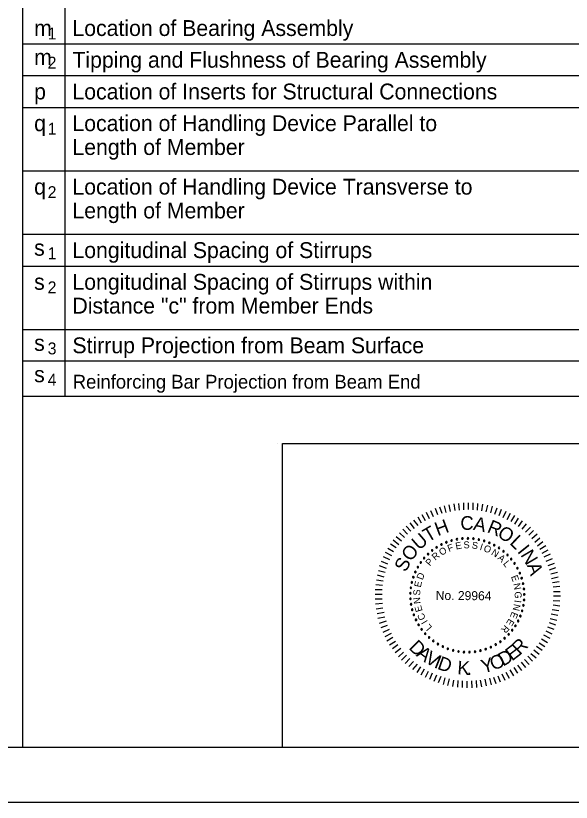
# Model space of a CAD drawing. Extents: x -55.6 to -19.5, y -5.1 to 16.9.
# Drawn here: x -35.36 to -30.34, y -5.09 to 2.04 of the extents above; entities that cross this region are included whole.
import ezdxf

# ---------------------------------------------------------------- set-up
doc = ezdxf.new("R2010")
doc.units = 0
for name, color, linetype in [('BR_BORDER LINES', 7, 'Continuous'), ('BR_TABLE LINES', 7, 'Continuous'), ('BR_TEXT', 7, 'Continuous'), ('Default', 7, 'Continuous'), ('Level 31', 7, 'Continuous')]:
    doc.layers.add(name, color=color, linetype=linetype)

msp = doc.modelspace()

# ---------------------------------------------------------------- linework, layer by layer
at = {"layer": 'BR_BORDER LINES'}
for p, q in [((-35.3047, 8.7992), (-35.3047, -4.5917)), ((-35.3047, -1.4104), (-25.9542, -1.4104)), ((-32.9495, -1.8415), (-27.5843, -1.8415)), ((-32.9495, -4.5916), (-32.9495, -1.8415)), ((-53.7501, -4.5917), (-20.084, -4.5917))]:
    msp.add_line(p, q, dxfattribs=at)
at = {"layer": 'BR_TABLE LINES'}
for p, q in [((-34.9214, 8.7992), (-34.9214, -1.4104)), ((-35.3047, 1.7804), (-25.9542, 1.7804)), ((-35.3047, 1.4929), (-25.9542, 1.4929)), ((-35.3047, 1.2054), (-25.9542, 1.2054)), ((-35.3047, 0.6304), (-25.9542, 0.6304)), ((-35.3047, 0.0554), (-25.9542, 0.0554)), ((-35.3047, -0.2321), (-25.9542, -0.2321)), ((-35.3047, -0.8071), (-25.9542, -0.8071)), ((-35.3047, -1.0912), (-25.9542, -1.0912))]:
    msp.add_line(p, q, dxfattribs=at)
at = {"layer": 'BR_TEXT'}
for p, q in [((-31.5048, -2.4758), (-31.5266, -2.4182)), ((-31.4686, -2.4658), (-31.4818, -2.4048)), ((-31.4273, -2.4559), (-31.4415, -2.3966)), ((-31.3878, -2.4485), (-31.3967, -2.3875)), ((-31.3483, -2.4445), (-31.3521, -2.3836)), ((-31.3088, -2.4423), (-31.3083, -2.3779)), ((-31.2667, -2.4401), (-31.2662, -2.3783)), ((-31.2247, -2.443), (-31.2224, -2.3786)), ((-31.1844, -2.4459), (-31.1796, -2.385)), ((-31.1458, -2.4505), (-31.135, -2.3897)), ((-31.1055, -2.4586), (-31.0913, -2.3994)), ((-31.0645, -2.4692), (-31.0485, -2.4084)), ((-31.0276, -2.4798), (-31.0057, -2.4225)), ((-31.6546, -2.5398), (-31.685, -2.4855)), ((-31.6201, -2.5221), (-31.6463, -2.4661)), ((-31.5831, -2.5052), (-31.6067, -2.4493)), ((-31.5443, -2.4884), (-31.5653, -2.4299)), ((-30.9883, -2.493), (-30.9663, -2.4348)), ((-30.9524, -2.5105), (-30.9245, -2.4549)), ((-30.9165, -2.5279), (-30.8851, -2.4724)), ((-30.8788, -2.5463), (-30.8466, -2.4924)), ((-31.7547, -2.6102), (-31.7946, -2.5601)), ((-31.721, -2.5848), (-31.7601, -2.5338)), ((-31.69, -2.5636), (-31.7204, -2.5092)), ((-30.8456, -2.5705), (-30.8117, -2.5167)), ((-30.8123, -2.5923), (-30.7758, -2.5419)), ((-31.817, -2.662), (-31.8612, -2.6179)), ((-31.7876, -2.6348), (-31.8292, -2.5899)), ((-30.7799, -2.6183), (-30.7392, -2.5688)), ((-30.7484, -2.6434), (-30.7051, -2.5992)), ((-30.7203, -2.6711), (-30.677, -2.6277)), ((-31.8715, -2.7243), (-31.921, -2.6852)), ((-31.8464, -2.6927), (-31.8898, -2.6503)), ((-30.6922, -2.7023), (-30.6447, -2.6606)), ((-30.665, -2.7342), (-30.6184, -2.696)), ((-31.9192, -2.7865), (-31.973, -2.7535)), ((-31.8975, -2.7575), (-31.947, -2.7176)), ((-30.6412, -2.7679), (-30.592, -2.7288)), ((-30.6192, -2.7972), (-30.5666, -2.7651)), ((-31.961, -2.8574), (-32.0174, -2.8295)), ((-31.9436, -2.8232), (-31.9974, -2.791)), ((-30.5972, -2.8343), (-30.5437, -2.803)), ((-30.5794, -2.8688), (-30.5217, -2.8418)), ((-31.996, -2.9326), (-32.0541, -2.9107)), ((-31.9785, -2.8942), (-32.0358, -2.8688)), ((-30.5617, -2.9059), (-30.5049, -2.8814)), ((-32.0083, -2.9729), (-32.0699, -2.9501)), ((-30.5449, -2.9446), (-30.4881, -2.9236)), ((-30.5315, -2.985), (-30.4738, -2.9632)), ((-32.0279, -3.0508), (-32.0904, -3.0349)), ((-32.0206, -3.0088), (-32.0815, -2.9937)), ((-30.5215, -3.0212), (-30.4613, -3.0071)), ((-30.5133, -3.0633), (-30.453, -3.0484)), ((-32.0431, -3.1279), (-32.1048, -3.1206)), ((-32.0384, -3.0868), (-32.0993, -3.0785)), ((-30.5049, -3.0994), (-30.4457, -3.0922)), ((-30.4984, -3.1407), (-30.4374, -3.1343)), ((-32.046, -3.1674), (-32.1103, -3.1668)), ((-30.4971, -3.1802), (-30.437, -3.1807)), ((-32.0467, -3.2515), (-32.111, -3.2526)), ((-32.048, -3.2085), (-32.1107, -3.208)), ((-30.4977, -3.2642), (-30.4377, -3.2665)), ((-30.4948, -3.2213), (-30.4339, -3.2218)), ((-32.0444, -3.2901), (-32.1062, -3.2973)), ((-32.0404, -3.3313), (-32.1015, -3.3403)), ((-30.507, -3.344), (-30.4479, -3.3539)), ((-30.4998, -3.3029), (-30.4389, -3.3111)), ((-32.0305, -3.3709), (-32.0932, -3.3841)), ((-32.024, -3.413), (-32.085, -3.4271)), ((-30.5159, -3.3834), (-30.4559, -3.3976)), ((-32.0123, -3.45), (-32.0742, -3.4709)), ((-32.0006, -3.4887), (-32.0591, -3.5097)), ((-30.5354, -3.4622), (-30.4781, -3.4841)), ((-30.5248, -3.4254), (-30.4649, -3.4405)), ((-31.9837, -3.5257), (-32.0414, -3.5527)), ((-31.9669, -3.5619), (-32.0237, -3.5915)), ((-30.5669, -3.5374), (-30.5105, -3.5653)), ((-30.5495, -3.5007), (-30.493, -3.5226)), ((-31.95, -3.599), (-32.0043, -3.6303)), ((-30.6036, -3.6101), (-30.5506, -3.6423)), ((-30.5853, -3.5733), (-30.528, -3.6038)), ((-31.9263, -3.6361), (-31.9806, -3.6674)), ((-31.905, -3.6654), (-31.9551, -3.7019)), ((-31.8796, -3.6991), (-31.9297, -3.7382)), ((-30.6487, -3.6758), (-30.6001, -3.7131)), ((-30.6262, -3.6468), (-30.5741, -3.679)), ((-31.855, -3.7328), (-31.8991, -3.7736)), ((-31.826, -3.7588), (-31.871, -3.8039)), ((-30.7293, -3.7678), (-30.6868, -3.8136)), ((-30.7008, -3.7423), (-30.6539, -3.7839)), ((-30.6731, -3.7091), (-30.6271, -3.7489)), ((-31.7971, -3.789), (-31.8395, -3.835)), ((-31.7647, -3.815), (-31.8054, -3.8619)), ((-31.7314, -3.8411), (-31.7713, -3.8888)), ((-30.8227, -3.8486), (-30.787, -3.8969)), ((-30.7898, -3.8231), (-30.7499, -3.8706)), ((-30.7579, -3.7976), (-30.7154, -3.8443)), ((-31.7007, -3.8628), (-31.732, -3.9148)), ((-31.6657, -3.8854), (-31.697, -3.9392)), ((-31.6315, -3.9054), (-31.6586, -3.961)), ((-30.9279, -3.9112), (-30.8975, -3.9672)), ((-30.89, -3.8918), (-30.8587, -3.9461)), ((-30.8563, -3.8698), (-30.8233, -3.9223)), ((-31.5948, -3.9228), (-31.6193, -3.9784)), ((-31.5563, -3.9403), (-31.5782, -3.9968)), ((-31.5169, -3.9527), (-31.5398, -4.0108)), ((-31.481, -3.965), (-31.4952, -4.0241)), ((-31.4399, -3.9722), (-31.455, -4.0339)), ((-31.4005, -3.9837), (-31.4104, -4.0419)), ((-31.361, -3.9883), (-31.3659, -4.05)), ((-31.3216, -3.9912), (-31.3221, -4.053)), ((-31.1972, -3.9896), (-31.1934, -4.0515)), ((-31.1585, -3.9857), (-31.1487, -4.0441)), ((-31.1181, -3.9748), (-31.1049, -4.0368)), ((-31.0768, -3.9683), (-31.0618, -4.0277)), ((-31.0398, -3.9566), (-31.0189, -4.0151)), ((-31.0003, -3.9449), (-30.9793, -4.0017)), ((-30.9641, -3.9281), (-30.9371, -3.9841)), ((-31.2796, -3.9941), (-31.2801, -4.0551)), ((-31.2375, -3.9919), (-31.2363, -4.0537))]:
    msp.add_line(p, q, dxfattribs=at)
for centre, start, end in [((-31.3702, -2.7086), 10.60376, 190.60376), ((-31.3702, -2.7086), 190.60376, 10.60376), ((-31.3208, -2.7019), 5.06529, 185.06529), ((-31.3208, -2.7019), 185.06529, 5.06529), ((-31.271, -2.7), 359.52683, 179.52683), ((-31.271, -2.7), 179.52683, 359.52683), ((-31.2213, -2.7029), 353.98837, 173.98837), ((-31.2213, -2.7029), 173.98837, 353.98837), ((-31.1721, -2.7106), 348.44991, 168.44991), ((-31.5545, -2.7814), 32.7576, 212.7576), ((-31.5545, -2.7814), 212.7576, 32.7576), ((-31.5113, -2.7566), 27.21914, 207.21914), ((-31.5113, -2.7566), 207.21914, 27.21914), ((-31.4659, -2.7361), 21.68068, 201.68068), ((-31.4659, -2.7361), 201.68068, 21.68068), ((-31.4187, -2.72), 16.14222, 196.14222), ((-31.4187, -2.72), 196.14222, 16.14222), ((-31.1721, -2.7106), 168.44991, 348.44991), ((-31.1238, -2.723), 162.91145, 342.91145), ((-31.1238, -2.723), 342.91145, 162.91145), ((-31.077, -2.74), 157.37299, 337.37299), ((-31.077, -2.74), 337.37299, 157.37299), ((-31.032, -2.7615), 151.83453, 331.83453), ((-31.032, -2.7615), 331.83453, 151.83453), ((-31.6327, -2.843), 43.83453, 223.83453), ((-31.6327, -2.843), 223.83453, 43.83453), ((-31.5951, -2.8103), 38.29606, 218.29606), ((-31.5951, -2.8103), 218.29606, 38.29606), ((-30.9893, -2.7872), 146.29606, 326.29606), ((-30.9893, -2.7872), 326.29606, 146.29606), ((-30.9493, -2.8169), 140.7576, 320.7576), ((-30.9493, -2.8169), 320.7576, 140.7576), ((-30.9123, -2.8503), 135.21914, 315.21914), ((-30.9123, -2.8503), 315.21914, 135.21914), ((-31.6977, -2.9184), 54.91145, 234.91145), ((-31.6977, -2.9184), 234.91145, 54.91145), ((-31.667, -2.8791), 49.37299, 229.37299), ((-31.667, -2.8791), 229.37299, 49.37299), ((-30.8788, -2.8872), 129.68068, 309.68068), ((-30.8788, -2.8872), 309.68068, 129.68068), ((-30.8489, -2.9271), 124.14222, 304.14222), ((-30.8489, -2.9271), 304.14222, 124.14222), ((-31.7244, -2.9604), 60.44991, 240.44991), ((-31.7244, -2.9604), 240.44991, 60.44991), ((-30.8231, -2.9697), 118.60376, 298.60376), ((-30.8231, -2.9697), 298.60376, 118.60376), ((-31.7651, -3.0513), 71.52683, 251.52683), ((-31.7651, -3.0513), 251.52683, 71.52683), ((-31.747, -3.0049), 65.98837, 245.98837), ((-31.747, -3.0049), 245.98837, 65.98837), ((-30.8014, -3.0146), 113.06529, 293.06529), ((-30.8014, -3.0146), 293.06529, 113.06529), ((-30.7842, -3.0613), 107.52683, 287.52683), ((-30.7842, -3.0613), 287.52683, 107.52683), ((-31.7787, -3.0992), 77.06529, 257.06529), ((-31.7787, -3.0992), 257.06529, 77.06529), ((-30.7716, -3.1095), 101.98837, 281.98837), ((-30.7716, -3.1095), 281.98837, 101.98837), ((-31.7917, -3.1979), 88.14222, 268.14222), ((-31.7876, -3.1483), 82.60376, 262.60376), ((-31.7917, -3.1979), 268.14222, 88.14222), ((-31.7876, -3.1483), 262.60376, 82.60376), ((-30.7638, -3.1587), 96.44991, 276.44991), ((-30.7607, -3.2085), 90.91145, 270.91145), ((-30.7638, -3.1587), 276.44991, 96.44991), ((-30.7607, -3.2085), 270.91145, 90.91145), ((-31.791, -3.2477), 93.68068, 273.68068), ((-31.791, -3.2477), 273.68068, 93.68068), ((-30.7624, -3.2583), 85.37299, 265.37299), ((-30.7624, -3.2583), 265.37299, 85.37299), ((-31.7855, -3.2973), 99.21914, 279.21914), ((-31.7855, -3.2973), 279.21914, 99.21914), ((-31.7753, -3.346), 104.7576, 284.7576), ((-31.7753, -3.346), 284.7576, 104.7576), ((-30.7801, -3.3562), 74.29606, 254.29606), ((-30.7801, -3.3562), 254.29606, 74.29606), ((-30.7689, -3.3077), 79.83453, 259.83453), ((-30.7689, -3.3077), 259.83453, 79.83453), ((-31.7604, -3.3936), 110.29606, 290.29606), ((-31.7604, -3.3936), 290.29606, 110.29606), ((-30.796, -3.4035), 68.7576, 248.7576), ((-30.796, -3.4035), 248.7576, 68.7576), ((-31.7409, -3.4395), 115.83453, 295.83453), ((-31.7409, -3.4395), 295.83453, 115.83453), ((-31.7171, -3.4833), 121.37299, 301.37299), ((-31.7171, -3.4833), 301.37299, 121.37299), ((-30.841, -3.4922), 57.68068, 237.68068), ((-30.841, -3.4922), 237.68068, 57.68068), ((-30.8164, -3.4489), 63.21914, 243.21914), ((-30.8164, -3.4489), 243.21914, 63.21914), ((-31.6893, -3.5246), 126.91145, 306.91145), ((-31.6893, -3.5246), 306.91145, 126.91145), ((-31.6575, -3.563), 132.44991, 312.44991), ((-31.6575, -3.563), 312.44991, 132.44991), ((-30.8698, -3.533), 52.14222, 232.14222), ((-30.8698, -3.533), 232.14222, 52.14222), ((-31.6222, -3.5981), 137.98837, 317.98837), ((-31.6222, -3.5981), 317.98837, 137.98837), ((-31.5837, -3.6297), 143.52683, 323.52683), ((-31.5837, -3.6297), 323.52683, 143.52683), ((-30.9775, -3.636), 35.52683, 215.52683), ((-30.9775, -3.636), 215.52683, 35.52683), ((-30.9383, -3.6052), 41.06529, 221.06529), ((-30.9383, -3.6052), 221.06529, 41.06529), ((-30.9023, -3.5707), 46.60376, 226.60376), ((-30.9023, -3.5707), 226.60376, 46.60376), ((-31.5423, -3.6575), 149.06529, 329.06529), ((-31.5423, -3.6575), 329.06529, 149.06529), ((-31.4984, -3.6811), 154.60376, 334.60376), ((-31.4984, -3.6811), 334.60376, 154.60376), ((-31.4525, -3.7003), 160.14222, 340.14222), ((-31.4525, -3.7003), 340.14222, 160.14222), ((-31.1101, -3.7039), 18.91145, 198.91145), ((-31.1101, -3.7039), 198.91145, 18.91145), ((-31.0638, -3.6855), 24.44991, 204.44991), ((-31.0638, -3.6855), 204.44991, 24.44991), ((-31.0194, -3.6628), 29.98837, 209.98837), ((-31.0194, -3.6628), 209.98837, 29.98837), ((-31.4049, -3.7151), 165.68068, 345.68068), ((-31.4049, -3.7151), 345.68068, 165.68068), ((-31.356, -3.7252), 171.21914, 351.21914), ((-31.356, -3.7252), 351.21914, 171.21914), ((-31.3065, -3.7305), 356.7576, 176.7576), ((-31.3065, -3.7305), 176.7576, 356.7576), ((-31.2567, -3.731), 2.29606, 182.29606), ((-31.2567, -3.731), 182.29606, 2.29606), ((-31.207, -3.7267), 7.83453, 187.83453), ((-31.207, -3.7267), 187.83453, 7.83453), ((-31.158, -3.7176), 13.37299, 193.37299), ((-31.158, -3.7176), 193.37299, 13.37299)]:
    msp.add_arc(centre, 0.00701, start, end, dxfattribs=at)
at = {"layer": 'Default'}
msp.add_line((-32.9929, -1.8417), (-32.9929, -1.8417), dxfattribs=at)
at = {"layer": 'Level 31'}
msp.add_lwpolyline([(-55.5834, -5.0916), (-19.5834, -5.0916), (-19.5834, 16.9084), (-55.5834, 16.9084)], close=True, dxfattribs=at)

# ---------------------------------------------------------------- texts
at = {"layer": 'BR_TEXT'}
for s, height, p in [('Location of Bearing Assembly', 0.14375, (-34.8516, 1.8523)), ('m', 0.1437, (-35.1983, 1.8523)), ('1', 0.1078, (-35.0759, 1.8205)), ('Tipping and Flushness of Bearing Assembly', 0.14375, (-34.8516, 1.5648)), ('m', 0.1437, (-35.1983, 1.5884)), ('2', 0.1078, (-35.0759, 1.5566)), ('Location of Inserts for Structural Connections', 0.14375, (-34.8516, 1.2773)), ('p', 0.1437, (-35.1983, 1.2773)), ('Location of Handling Device Parallel to', 0.14375, (-34.8516, 0.9898)), ('q', 0.1437, (-35.1983, 0.9898)), ('1', 0.1078, (-35.0759, 0.958)), ('Length of Member', 0.14375, (-34.8516, 0.7741)), ('q', 0.1437, (-35.1983, 0.4148)), ('Location of Handling Device Transverse to', 0.14375, (-34.8516, 0.4148)), ('2', 0.1078, (-35.0759, 0.383)), ('Length of Member', 0.14375, (-34.8516, 0.1991)), ('s', 0.1437, (-35.1983, -0.1386)), ('1', 0.1078, (-35.0759, -0.1704)), ('Longitudinal Spacing of Stirrups', 0.14375, (-34.8516, -0.1602)), ('s', 0.1437, (-35.1983, -0.4477)), ('Longitudinal Spacing of Stirrups within', 0.14375, (-34.8516, -0.4477)), ('2', 0.1078, (-35.0759, -0.4795)), ('Distance "c" from Member Ends', 0.14375, (-34.8516, -0.6634)), ('s', 0.1437, (-35.1983, -1.0011)), ('3', 0.1078, (-35.0759, -1.0329)), ('Stirrup Projection from Beam Surface', 0.14375, (-34.8516, -1.0227)), ('s', 0.1437, (-35.1983, -1.2852)), ('4', 0.1078, (-35.0759, -1.317)), ('Reinforcing Bar Projection from Beam End', 0.125, (-34.8487, -1.3432))]:
    msp.add_text(s, height=height, dxfattribs=at).set_placement(p)
for s, height, rotation, p in [('H', 0.1241, 20.36371, (-31.5439, -2.6807)), ('C', 0.1241, 359.54822, (-31.3395, -2.6224)), ('A', 0.1241, 348.19813, (-31.2281, -2.6216)), ('R', 0.1241, 337.43439, (-31.1048, -2.6415)), ('T', 0.1241, 30.49921, (-31.6318, -2.7382)), ('O', 0.1239, 326.58689, (-31.0126, -2.6782)), ('U', 0.1241, 40.80225, (-31.713, -2.813)), ('L', 0.1241, 315.94879, (-30.9, -2.746)), ('O', 0.1241, 52.0267, (-31.7876, -2.9169)), ('F', 0.0622, 20.61271, (-31.4427, -2.8236)), ('E', 0.0622, 11.41035, (-31.3775, -2.8019)), ('S', 0.0622, 2.20798, (-31.3097, -2.7909)), ('S', 0.0622, 352.66081, (-31.2384, -2.7911)), ('I', 0.0622, 343.11363, (-31.1682, -2.8032)), ('O', 0.0622, 338.43918, (-31.1347, -2.8133)), ('I', 0.1241, 308.66128, (-30.8287, -2.8203)), ('R', 0.0622, 40.39491, (-31.5662, -2.9035)), ('O', 0.0622, 30.84774, (-31.51, -2.8596)), ('N', 0.0622, 328.20415, (-31.0651, -2.8447)), ('N', 0.1241, 300.70365, (-30.7981, -2.8497)), ('S', 0.1239, 63.25114, (-31.8329, -3.0125)), ('P', 0.0622, 49.94209, (-31.6143, -2.9561)), ('A', 0.0622, 318.65698, (-31.0061, -2.8847)), ('L', 0.0622, 309.45461, (-30.9564, -2.932)), ('A', 0.1241, 289.47921, (-30.7388, -2.9427)), ('D', 0.0622, 69.03644, (-31.6812, -3.0814)), ('E', 0.0622, 291.049, (-30.8825, -3.0474)), ('E', 0.0622, 78.23881, (-31.6978, -3.148)), ('N', 0.0622, 281.84664, (-30.8603, -3.1124)), ('S', 0.0622, 87.78598, (-31.7035, -3.2191)), ('No. 29964', 0.08175, 359.52683, (-31.5624, -3.2575)), ('G', 0.0622, 272.29946, (-30.8486, -3.1827)), ('N', 0.0622, 97.33316, (-31.6973, -3.2901)), ('I', 0.0622, 262.40836, (-30.8489, -3.2565)), ('E', 0.0622, 106.53552, (-31.6803, -3.3566)), ('N', 0.0622, 257.73391, (-30.8535, -3.2911)), ('C', 0.0622, 116.42662, (-31.6504, -3.4241)), ('E', 0.0622, 248.18673, (-30.8715, -3.3601)), ('I', 0.0622, 121.10107, (-31.6324, -3.454)), ('L', 0.0622, 129.95951, (-31.5917, -3.5062)), ('R', 0.0622, 229.78201, (-30.9371, -3.4803)), ('E', 0.0622, 238.98437, (-30.8994, -3.4228)), ('D', 0.1236, 315.40526, (-31.8122, -3.6968)), ('R', 0.1236, 44.59474, (-30.8013, -3.7624)), ('A', 0.1236, 322.83772, (-31.7456, -3.7624)), ('E', 0.1236, 37.53391, (-30.872, -3.8163)), ('V', 0.1236, 330.51792, (-31.6685, -3.8206)), ('I', 0.1236, 338.19813, (-31.5842, -3.868)), ('D', 0.1236, 340.79949, (-31.5544, -3.8814)), ('O', 0.1236, 22.42125, (-31.0421, -3.9002)), ('D', 0.1236, 30.10145, (-30.9529, -3.8632)), ('K', 0.1236, 356.09796, (-31.3691, -3.932)), ('Y', 0.1236, 14.86491, (-31.134, -3.9247)), ('.', 0.1236, 3.15879, (-31.2805, -3.9383))]:
    msp.add_text(s, height=height, rotation=rotation, dxfattribs=at).set_placement(p)

doc.saveas('drawing.dxf')
